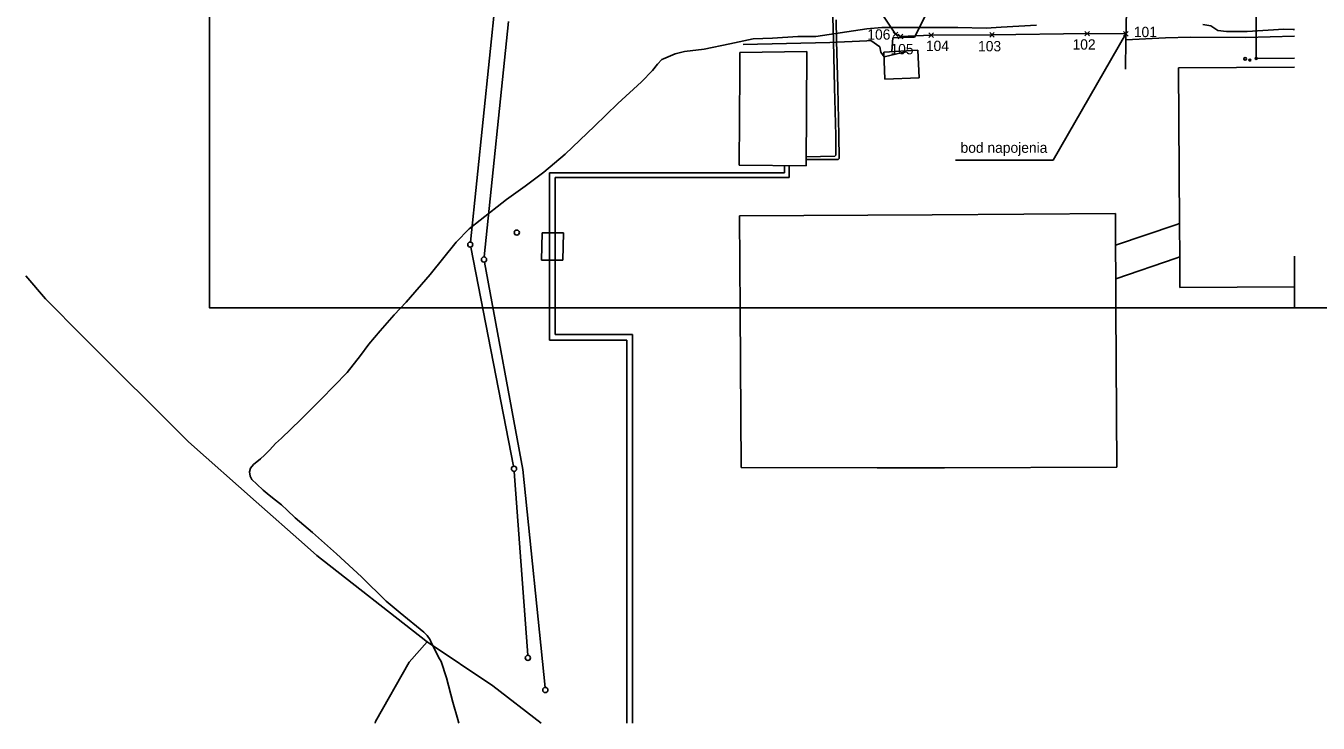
# Model space of a CAD drawing. Extents: x -264205 to -263744, y -1242450 to -1242050.
# Drawn here: x -264200 to -263949.9, y -1242450 to -1242315 of the extents above; entities that cross this region are included whole.
import ezdxf

# ---------------------------------------------------------------- set-up
doc = ezdxf.new("R2010")
doc.units = 0
for name, color, linetype in [('KFA_63-1_TELEKOM_PRELOZKA', 7, 'Continuous'), ('KFA_BODY_CISLO', 7, 'Continuous'), ('KFA_BODY_SYMBOL', 7, 'Continuous'), ('KFA_JESTV_IS_DSP', 7, 'Continuous'), ('KFA_SITUACIA_DSP', 7, 'Continuous'), ('KFA_TELEKOM_POVODNA_TRASA', 7, 'Continuous'), ('POPIS', 7, 'Continuous'), ('RAM_NA_TLAC_A3_1-1000', 7, 'Continuous')]:
    doc.layers.add(name, color=color, linetype=linetype)

msp = doc.modelspace()

# ---------------------------------------------------------------- linework, layer by layer
at = {"layer": 'KFA_63-1_TELEKOM_PRELOZKA'}
msp.add_lwpolyline([(-263987.08, -1242316.53), (-263994.57, -1242316.5), (-264012.99, -1242316.72), (-264024.76, -1242316.81), (-264030.71, -1242317.07), (-264031.69, -1242316.63), (-264035.64, -1242310.62)], dxfattribs=at)
at = {"layer": 'KFA_BODY_SYMBOL'}
for p, q in [((-263995.01, -1242316.95), (-263994.13, -1242316.06)), ((-263994.13, -1242316.95), (-263995.01, -1242316.06)), ((-263987.52, -1242316.97), (-263986.64, -1242316.08)), ((-263986.64, -1242316.97), (-263987.52, -1242316.08)), ((-264032.13, -1242317.07), (-264031.24, -1242316.19)), ((-264031.24, -1242317.07), (-264032.13, -1242316.19)), ((-264031.69, -1242316.63), (-264031.69, -1242316.63)), ((-264031.15, -1242317.51), (-264030.27, -1242316.63)), ((-264030.27, -1242317.51), (-264031.15, -1242316.63)), ((-264030.71, -1242317.07), (-264030.71, -1242317.07)), ((-264025.2, -1242317.25), (-264024.32, -1242316.37)), ((-264024.32, -1242317.25), (-264025.2, -1242316.37)), ((-264024.76, -1242316.81), (-264024.76, -1242316.81)), ((-264013.44, -1242317.17), (-264012.55, -1242316.28)), ((-264012.55, -1242317.17), (-264013.44, -1242316.28)), ((-264012.99, -1242316.72), (-264012.99, -1242316.72)), ((-263994.57, -1242316.5), (-263994.57, -1242316.5)), ((-263987.08, -1242316.53), (-263987.08, -1242316.53))]:
    msp.add_line(p, q, dxfattribs=at)
at = {"layer": 'KFA_JESTV_IS_DSP'}
for p, q in [((-263961.97, -1242257), (-263961.85, -1242321.3)), ((-264107.35, -1242293.45), (-264113.93, -1242356.84)), ((-264022.91, -1242307.11), (-264028.02, -1242317.15)), ((-264043.78, -1242313.27), (-264043.67, -1242317.93)), ((-264106.61, -1242314.15), (-264111.27, -1242359.73)), ((-264047.11, -1242317.03), (-264037.23, -1242315.56)), ((-264043.1, -1242317.89), (-264043.16, -1242313.81)), ((-264037.23, -1242315.56), (-264034.31, -1242315.31)), ((-264034.31, -1242315.31), (-264029.89, -1242315.32)), ((-264029.89, -1242315.32), (-264024.65, -1242315.29)), ((-264024.65, -1242315.29), (-264019.6, -1242315.33)), ((-264019.6, -1242315.33), (-264014.13, -1242315.41)), ((-264014.13, -1242315.41), (-264011.19, -1242315.25)), ((-264011.19, -1242315.25), (-264004.4, -1242314.87)), ((-263972.17, -1242314.7), (-263970.63, -1242314.99)), ((-263970.63, -1242314.99), (-263969.31, -1242315.89)), ((-263969.31, -1242315.89), (-263967.63, -1242316.08)), ((-263967.63, -1242316.08), (-263963.59, -1242316.09)), ((-263963.59, -1242316.09), (-263956.5, -1242315.61)), ((-263956.5, -1242315.61), (-263954.68, -1242315.7)), ((-263954.68, -1242315.7), (-263954.47, -1242315.7)), ((-264068.7, -1242319.48), (-264063.75, -1242318.45)), ((-264063.75, -1242318.45), (-264059.23, -1242317.5)), ((-264061.14, -1242318.59), (-264044.39, -1242318.22)), ((-264059.23, -1242317.5), (-264055.45, -1242317.35)), ((-264055.45, -1242317.35), (-264050.57, -1242317.07)), ((-264050.57, -1242317.07), (-264047.11, -1242317.03)), ((-264044.39, -1242318.22), (-264037.22, -1242317.89)), ((-264043.67, -1242317.93), (-264043.45, -1242326.93)), ((-264042.85, -1242326.92), (-264043.1, -1242317.89)), ((-264037.22, -1242317.89), (-264036.44, -1242317.83)), ((-264036.44, -1242317.83), (-264034.73, -1242319.08)), ((-264032.17, -1242317.31), (-264032.39, -1242319.93)), ((-264028.02, -1242317.15), (-264032.17, -1242317.31)), ((-263987.11, -1242317.68), (-263979.4, -1242317.34)), ((-263979.4, -1242317.34), (-263974.58, -1242317.17)), ((-263974.58, -1242317.17), (-263963.87, -1242317.22)), ((-263963.87, -1242317.22), (-263954.47, -1242317)), ((-264076.59, -1242321.35), (-264074.3, -1242320.41)), ((-264074.3, -1242320.41), (-264072.53, -1242319.96)), ((-264072.53, -1242319.96), (-264068.7, -1242319.48)), ((-264034.73, -1242319.08), (-264034.52, -1242320.11)), ((-264034.52, -1242320.11), (-264033.86, -1242320.96)), ((-264033.86, -1242320.96), (-264030.57, -1242320.23)), ((-264030.57, -1242320.23), (-264029.56, -1242320)), ((-264080.85, -1242325.81), (-264078.68, -1242323.64)), ((-264078.68, -1242323.64), (-264077.73, -1242322.4)), ((-264077.73, -1242322.4), (-264076.93, -1242321.5)), ((-264076.93, -1242321.5), (-264076.59, -1242321.35)), ((-263961.85, -1242321.3), (-263954.47, -1242321.26)), ((-263961.85, -1242321.3), (-263961.85, -1242321.3)), ((-264085.4, -1242330.05), (-264080.85, -1242325.81)), ((-264043.45, -1242326.93), (-264043.24, -1242336.19)), ((-264042.63, -1242336.24), (-264042.85, -1242326.92)), ((-264089.92, -1242334.43), (-264085.4, -1242330.05)), ((-264095.59, -1242339.81), (-264089.92, -1242334.43)), ((-264043.24, -1242336.19), (-264043.19, -1242340.02)), ((-264042.55, -1242340.64), (-264042.63, -1242336.24)), ((-264099.74, -1242343.3), (-264095.59, -1242339.81)), ((-264043.42, -1242340.24), (-264048.98, -1242340.34)), ((-264048.98, -1242340.84), (-264042.76, -1242340.87)), ((-264043.19, -1242340.02), (-264043.42, -1242340.24)), ((-264042.76, -1242340.87), (-264042.55, -1242340.64)), ((-264103.34, -1242346.03), (-264099.74, -1242343.3)), ((-264098.66, -1242343.45), (-264098.66, -1242375.85)), ((-264098.66, -1242343.45), (-264053.17, -1242343.45)), ((-264053.17, -1242342.19), (-264053.17, -1242343.45)), ((-264052.24, -1242342.19), (-264052.24, -1242344.34)), ((-264106.94, -1242348.61), (-264103.34, -1242346.03)), ((-264097.56, -1242344.34), (-264097.56, -1242374.75)), ((-264097.56, -1242344.34), (-264052.24, -1242344.34)), ((-264112.04, -1242352.6), (-264106.94, -1242348.61)), ((-264114.2, -1242354.26), (-264112.04, -1242352.6)), ((-264116.7, -1242356.85), (-264114.2, -1242354.26)), ((-264100.17, -1242360.35), (-264100.07, -1242355.05)), ((-264095.96, -1242355.04), (-264100.07, -1242355.05)), ((-264095.96, -1242355.04), (-264096.03, -1242360.36)), ((-264121.76, -1242363.16), (-264116.7, -1242356.85)), ((-264113.88, -1242357.83), (-264105.6, -1242400.26)), ((-264111.23, -1242360.72), (-264103.81, -1242400.89)), ((-264096.03, -1242360.36), (-264100.17, -1242360.35)), ((-264200, -1242363.4), (-264196.21, -1242367.82)), ((-264126.36, -1242368.51), (-264121.76, -1242363.16)), ((-264196.21, -1242367.82), (-264188.88, -1242375.19)), ((-264128.69, -1242370.91), (-264126.36, -1242368.51)), ((-264131.44, -1242374.02), (-264128.69, -1242370.91)), ((-264188.88, -1242375.19), (-264168.52, -1242395.55)), ((-264133.61, -1242376.59), (-264131.44, -1242374.02)), ((-264098.66, -1242375.85), (-264083.66, -1242375.85)), ((-264097.56, -1242374.75), (-264082.56, -1242374.75)), ((-264083.66, -1242375.85), (-264083.66, -1242450)), ((-264082.56, -1242374.75), (-264082.56, -1242450)), ((-264135.2, -1242378.82), (-264133.61, -1242376.59)), ((-264137.8, -1242382.11), (-264135.2, -1242378.82)), ((-264142.81, -1242387.25), (-264137.8, -1242382.11)), ((-264146.83, -1242391.28), (-264142.81, -1242387.25)), ((-264174.74, -1242389.33), (-264173.5, -1242390.57)), ((-264150.54, -1242394.8), (-264146.83, -1242391.28)), ((-264168.52, -1242395.55), (-264155.42, -1242407.15)), ((-264152.79, -1242397.07), (-264151.67, -1242395.84)), ((-264151.67, -1242395.84), (-264150.54, -1242394.8)), ((-264154.58, -1242398.8), (-264153.78, -1242398.09)), ((-264153.78, -1242398.09), (-264152.79, -1242397.07)), ((-264156.73, -1242401.31), (-264156.51, -1242400.61)), ((-264156.51, -1242400.61), (-264155.92, -1242399.93)), ((-264155.92, -1242399.93), (-264154.58, -1242398.8)), ((-264103.81, -1242400.89), (-264099.5, -1242443.09)), ((-264156.6, -1242402.17), (-264156.73, -1242401.31)), ((-264156.24, -1242402.81), (-264156.6, -1242402.17)), ((-264155.29, -1242403.75), (-264156.24, -1242402.81)), ((-264105.47, -1242401.25), (-264102.86, -1242436.86)), ((-264154.08, -1242404.89), (-264155.29, -1242403.75)), ((-264152.93, -1242405.83), (-264154.08, -1242404.89)), ((-264151.66, -1242406.83), (-264152.93, -1242405.83)), ((-264155.42, -1242407.15), (-264146.06, -1242415.44)), ((-264150.5, -1242407.72), (-264151.66, -1242406.83)), ((-264149.39, -1242408.73), (-264150.5, -1242407.72)), ((-264147.87, -1242410.23), (-264149.39, -1242408.73)), ((-264144.52, -1242413.09), (-264147.87, -1242410.23)), ((-264139.87, -1242417.24), (-264144.52, -1242413.09)), ((-264146.06, -1242415.44), (-264143.66, -1242417.56)), ((-264143.66, -1242417.56), (-264122.59, -1242434.03)), ((-264135.02, -1242421.64), (-264139.87, -1242417.24)), ((-264130.23, -1242426.38), (-264135.02, -1242421.64)), ((-264127.57, -1242428.67), (-264130.23, -1242426.38)), ((-264122.94, -1242432.35), (-264127.57, -1242428.67)), ((-264122.32, -1242433.02), (-264122.94, -1242432.35)), ((-264121.75, -1242433.87), (-264122.32, -1242433.02)), ((-264125.81, -1242438.16), (-264122.31, -1242434.25)), ((-264122.59, -1242434.03), (-264122.31, -1242434.25)), ((-264122.31, -1242434.25), (-264109.63, -1242442.78)), ((-264121.56, -1242434.41), (-264121.75, -1242433.87)), ((-264120.84, -1242435.74), (-264121.56, -1242434.41)), ((-264120.12, -1242437.23), (-264120.84, -1242435.74)), ((-264132.32, -1242449.69), (-264125.81, -1242438.16)), ((-264119.6, -1242438.07), (-264120.12, -1242437.23)), ((-264118.6, -1242441.21), (-264119.6, -1242438.07)), ((-264117.34, -1242445.92), (-264118.6, -1242441.21)), ((-264109.63, -1242442.78), (-264100.24, -1242450)), ((-264116.37, -1242449.3), (-264117.34, -1242445.92)), ((-264132.37, -1242450), (-264132.32, -1242449.69)), ((-264116.21, -1242450), (-264116.37, -1242449.3))]:
    msp.add_line(p, q, dxfattribs=at)
for centre, radius in [((-263963.98, -1242321.38), 0.25), ((-263961.85, -1242321.3), 0.179), ((-263963.07, -1242321.61), 0.179), ((-264104.97, -1242355.02), 0.5), ((-264113.98, -1242357.34), 0.5), ((-264111.32, -1242360.23), 0.5), ((-264105.51, -1242400.75), 0.5), ((-264102.82, -1242437.36), 0.5), ((-264099.45, -1242443.58), 0.5)]:
    msp.add_circle(centre, radius, dxfattribs=at)
at = {"layer": 'KFA_SITUACIA_DSP'}
for p, q in [((-264061.82, -1242323.92), (-264061.79, -1242320.14)), ((-264061.79, -1242320.14), (-264048.82, -1242319.93)), ((-264048.82, -1242319.93), (-264048.99, -1242342.09)), ((-264033.95, -1242320.06), (-264027.34, -1242319.71)), ((-264033.72, -1242325.32), (-264033.95, -1242320.06)), ((-264027.34, -1242319.71), (-264027.11, -1242325.04)), ((-263976.89, -1242323.14), (-263954.47, -1242322.99)), ((-263976.89, -1242323.14), (-263976.69, -1242353.26)), ((-264061.96, -1242341.99), (-264061.82, -1242323.92)), ((-264027.11, -1242325.04), (-264033.72, -1242325.32)), ((-264061.96, -1242341.99), (-264048.99, -1242342.09)), ((-264024.58, -1242351.56), (-264061.87, -1242351.8)), ((-264061.75, -1242370.08), (-264061.87, -1242351.8)), ((-264024.58, -1242351.56), (-263989.12, -1242351.34)), ((-263989.12, -1242351.34), (-263989.08, -1242357.47)), ((-263977.4, -1242353.5), (-263989.08, -1242357.47)), ((-263977.4, -1242353.5), (-263976.69, -1242353.26)), ((-263976.65, -1242359.72), (-263976.69, -1242353.26)), ((-263989.04, -1242363.95), (-263989.08, -1242357.47)), ((-263977.32, -1242359.95), (-263989.04, -1242363.95)), ((-263977.32, -1242359.95), (-263976.65, -1242359.72)), ((-263976.65, -1242359.72), (-263976.61, -1242365.64)), ((-263989.04, -1242363.95), (-263989.01, -1242369.66)), ((-263954.47, -1242365.5), (-263976.61, -1242365.64)), ((-264061.75, -1242370.08), (-264061.55, -1242400.48)), ((-263988.83, -1242400.42), (-263989.01, -1242369.66)), ((-264035.24, -1242400.55), (-264061.55, -1242400.48)), ((-264028.07, -1242400.56), (-264035.24, -1242400.55)), ((-264022.19, -1242400.57), (-264028.07, -1242400.56)), ((-263988.83, -1242400.42), (-264022.19, -1242400.57))]:
    msp.add_line(p, q, dxfattribs=at)
at = {"layer": 'KFA_TELEKOM_POVODNA_TRASA'}
for p, q in [((-263987.11, -1242317.68), (-263986.63, -1242298.98)), ((-263987.17, -1242323.4), (-263987.11, -1242317.68))]:
    msp.add_line(p, q, dxfattribs=at)
at = {"layer": 'POPIS'}
for p, q in [((-263987.08, -1242316.53), (-264001.13, -1242340.97)), ((-264001.13, -1242340.97), (-264020.05, -1242340.97))]:
    msp.add_line(p, q, dxfattribs=at)
at = {"layer": 'RAM_NA_TLAC_A3_1-1000'}
msp.add_line((-263954.47, -1242369.57), (-263954.47, -1242359.57), dxfattribs=at)
msp.add_lwpolyline([(-264164.47, -1242072.57), (-263744.47, -1242072.57), (-263744.47, -1242369.57), (-264164.47, -1242369.57)], close=True, dxfattribs=at)

# ---------------------------------------------------------------- texts
at = {"layer": 'KFA_BODY_CISLO'}
for s, p in [('106', (-264037.12, -1242317.66)), ('101', (-263985.54, -1242317.17)), ('105', (-264032.64, -1242320.5)), ('104', (-264025.79, -1242319.86)), ('103', (-264015.69, -1242319.92)), ('102', (-263997.4, -1242319.59))]:
    msp.add_text(s, height=2, dxfattribs=at).set_placement(p)
at = {"layer": 'POPIS'}
msp.add_text('bod napojenia', height=2, dxfattribs=at).set_placement((-264019.08, -1242339.57))

doc.saveas('drawing.dxf')
